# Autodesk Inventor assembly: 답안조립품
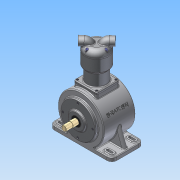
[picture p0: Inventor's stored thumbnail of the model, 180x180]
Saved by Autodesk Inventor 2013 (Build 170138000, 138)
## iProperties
Created: 2015-06
Part Number: 답안조립품
Document SubType Name: Assembly
Designer: ST5
Author: ST5
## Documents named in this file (15)
- C:\Users\ST5\Desktop\450605V1012\답안조립품.iam
- C:\Users\ST5\Desktop\450605V1012\1-본체.ipt
- C:\Users\ST5\Desktop\450605V1012\실린더.ipt
- C:\Users\ST5\Desktop\450605V1012\실린더헤드.ipt
- C:\Users\ST5\Desktop\450605V1012\메인커버.ipt
- C:\Users\ST5\Desktop\450605V1012\메인 크랭크 축-구동부.ipt
- C:\Users\ST5\Desktop\450605V1012\베어링 6204.ipt
- C:\Users\ST5\Desktop\450605V1012\크랭크 서브축.ipt
- C:\Users\ST5\Desktop\450605V1012\베어링 NA 4902.ipt
- C:\Users\ST5\Desktop\450605V1012\커넥팅 로드.ipt
- C:\Users\ST5\Desktop\450605V1012\피스톤.ipt
- C:\Users\ST5\Desktop\450605V1012\피스톤 핀.ipt
- C:\Users\ST5\Desktop\450605V1012\오일실.ipt
- C:\Users\ST5\Desktop\450605V1012\M5x0.8.ipt
- C:\Users\ST5\Desktop\450605V1012\M4x0.7.ipt
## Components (15 placed, 5 different names)
1. 1-본체:1
2. 피스톤:1
3. 피스톤 핀:1
4. M5x0.8:1
5. M5x0.8:2
6. M5x0.8:3
7. M5x0.8:4
8. M4x0.7:1
9. M4x0.7:3
10. M4x0.7:4
11. M4x0.7:5
12. M4x0.7:2
13. M4x0.7:6
14. M4x0.7:7
15. M4x0.7:8
